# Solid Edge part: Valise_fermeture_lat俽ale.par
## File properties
Author: Bernard DUMAS
Template: Normal.par
Last saved by: FR026244
Revision: 32
Application: Solid Edge
Densité: 7750.000 kg/m^3
Précision: 0.9900
Document Number: 14
Revision: a
Project Name: Slamson
Material: Acier inoxydable
Style de face: Argent
Style de remplissage: ANSI32(Acier)
Style virtuel: Acier inoxydable
Coef. of Thermal Exp: 0.0
Thermal Conductivity: 17.0
Specific Heat: 502.0
Modulus of Elasticity: 193053196000.0
Poission's Ratio: 0.29
Yield Stress: 310264065.0
Ultimate Stress: 641212401.0
Elongation: 0.0
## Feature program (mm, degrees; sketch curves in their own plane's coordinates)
sketch for "unnamed Protrusion 1" plane through (0, 0, 0) normal (0, -1, 0) x-axis (1, 0, 0)
extrude "unnamed Protrusion 1" add finite 5 along +normal
fillet "Congé_1" radius 2
sketch for "Ajout_matière_10" #1 plane through (0, -5, 0) normal (0, -1, 0) x-axis (1, 0, 0)
sketch for "Ajout_matière_10" #2 plane through (0, -5, 0) normal (0, -1, 0) x-axis (1, 0, 0)
extrude "Ajout_matière_10" add finite 3 along +normal
sketch for "unnamed Cutout 1" plane through (0, -5, 0) normal (0, -1, 0) x-axis (1, 0, 0)
extrude "unnamed Cutout 1" cut through along -normal
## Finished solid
Body 1: solid body, 18 faces, 36 edges, 20 vertices.
  Faces by surface: plane 12, cylinder 6
  Edges by curve: line 28, circle 4, ellipse 4
Bounding box of the edges (mm): 75.000 x 8.000 x 45.000, from (-37.5, -8, -22.5) to (37.5, 0, 22.5).
Cylindrical faces by radius (mm): R2 x4, R3.1303 x1, R12.5 x1
Planar faces by outward normal: +x 2, +y 1, +z 2, -x 2, -y 3, -z 2
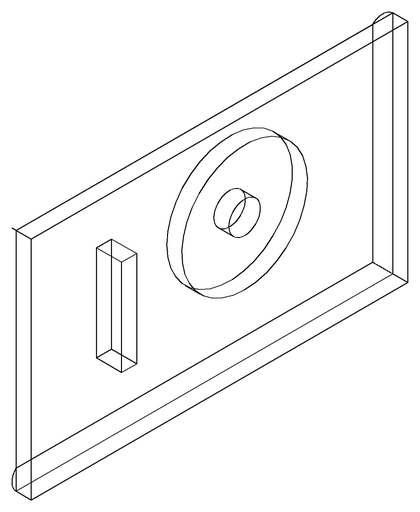
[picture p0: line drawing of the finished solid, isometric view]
